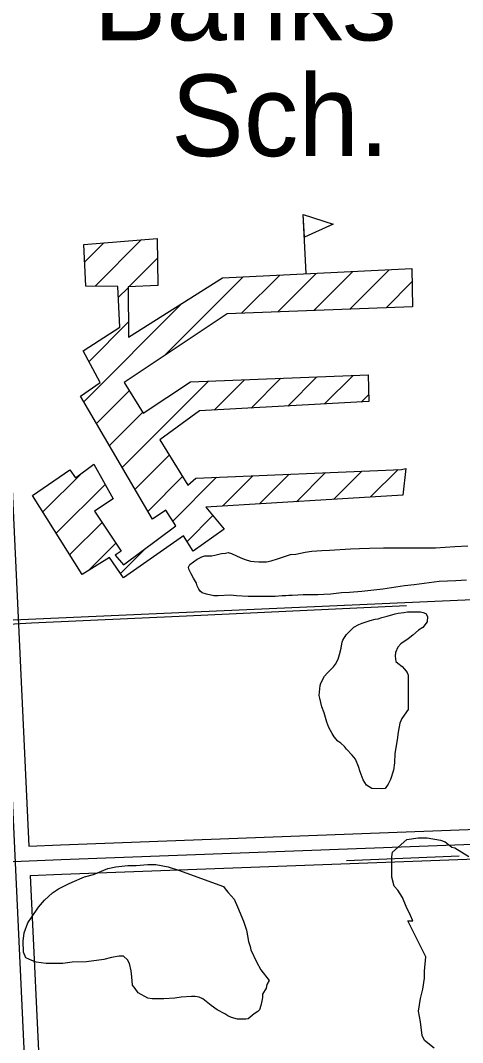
# Model space of a CAD drawing. Extents: x 3313442 to 3351311, y 721974 to 747360.
# Drawn here: x 3332744 to 3333194, y 732187 to 733227 of the extents above; entities that cross this region are included whole.
import ezdxf

# ---------------------------------------------------------------- set-up
doc = ezdxf.new("R2010")
doc.units = 0
for name, color, linetype in [('V-BLDG-IDEN', 7, 'Continuous'), ('V-BLDG-OTLN', 7, 'Continuous'), ('V-ROAD-CNTR', 7, 'Continuous'), ('V-SITE-VEGE', 7, 'Continuous')]:
    doc.layers.add(name, color=color, linetype=linetype)

msp = doc.modelspace()

# ---------------------------------------------------------------- linework, layer by layer
at = {"layer": 'V-BLDG-OTLN'}
for p, q in [((3333034.7, 732969.6), (3333031.7, 733029.6)), ((3332809.2, 732981.5), (3332828.5, 733000.8)), ((3332819.7, 732956.7), (3332867, 733004)), ((3332854.5, 732956.2), (3332883.1, 732984.8)), ((3333005.7, 732930.5), (3333044.8, 732969.7)), ((3333042.4, 732932), (3333082, 732971.5)), ((3333079.2, 732933.4), (3333119.2, 732973.3)), ((3332890.4, 732886), (3332970.5, 732966.1)), ((3332968.9, 732929.1), (3333007.7, 732967.9)), ((3333116, 732934.8), (3333142.5, 732961.3)), ((3332843.4, 732945), (3332853.4, 732955.1)), ((3332808.2, 732839.1), (3332908, 732938.9)), ((3332813.5, 732879.8), (3332853.6, 732919.9)), ((3333015.9, 732834.7), (3333045.6, 732864.4)), ((3333053.3, 732836.8), (3333082.3, 732865.8)), ((3332847.3, 732772.2), (3332935.3, 732860.1)), ((3332941.1, 732830.6), (3332972, 732861.5)), ((3332978.5, 732832.7), (3333008.8, 732863)), ((3332821.2, 732816.8), (3332854.5, 732850.1)), ((3333090.7, 732838.8), (3333098.3, 732846.4)), ((3332834.3, 732794.5), (3332868.2, 732828.4)), ((3332860.3, 732749.9), (3332895.2, 732784.8)), ((3332766.7, 732726.9), (3332806.2, 732766.5)), ((3332873.4, 732727.5), (3332908.8, 732762.9)), ((3332898.9, 732717.7), (3332943.4, 732762.2)), ((3332949.5, 732732.9), (3332980.3, 732763.8)), ((3332987.1, 732735.2), (3333017.3, 732765.4)), ((3333024.7, 732737.4), (3333054.2, 732767)), ((3333062.3, 732739.6), (3333091.2, 732768.6)), ((3333099.8, 732741.9), (3333128.2, 732770.2)), ((3332780.3, 732705.2), (3332830, 732754.9)), ((3332913.4, 732696.9), (3332939.7, 732723.2)), ((3332793.9, 732683.5), (3332826.8, 732716.3)), ((3332813.2, 732667.3), (3332840.9, 732695.1)), ((3332845.6, 732664.4), (3332870.4, 732689.2))]:
    msp.add_line(p, q, dxfattribs=at)
for points in [[(3333031.7, 733029.6), (3333062.2, 733019.6), (3333032.8, 733006.5)], [(3333133, 732743.9), (3332932.6, 732731.9), (3332951, 732709.5), (3332919.5, 732687.1), (3332909.8, 732702.7), (3332848.7, 732660), (3332834.4, 732680.6), (3332806.6, 732663.2), (3332756.2, 732743.7), (3332794, 732769.8), (3332799.9, 732761.7), (3332818.6, 732775.7), (3332838.2, 732740.2), (3332819.2, 732727.7), (3332846.2, 732687.2), (3332840.3, 732683.1), (3332848.7, 732673.1), (3332902, 732712.7), (3332891.8, 732728.9), (3332878.1, 732719.5), (3332805, 732844.6), (3332824.9, 732858.6), (3332807.5, 732891), (3332844.9, 732915), (3332842.8, 732956.4), (3332810.4, 732956.8), (3332808.3, 732999.2), (3332882.8, 733005.3), (3332883.6, 732957.3), (3332853.4, 732956.1), (3332853.7, 732904.7), (3332949.4, 732965), (3333142.3, 732974.5), (3333142.9, 732935.8), (3332954.3, 732928.6), (3332849.2, 732858.6), (3332868.8, 732827.4), (3332916.9, 732859.4), (3333097.6, 732866.4), (3333098.5, 732839.3), (3332925.9, 732829.8), (3332885.6, 732800.2), (3332914.2, 732754.1), (3332922.4, 732761.2), (3333131.5, 732770.3), (3333136.2, 732771)]]:
    msp.add_lwpolyline(points, close=True, dxfattribs=at)
at = {"layer": 'V-ROAD-CNTR'}
for p, q in [((3332912.7, 732621.1), (3333136.8, 732631.6)), ((3333075.8, 732372.4), (3333190.4, 732377))]:
    msp.add_line(p, q, dxfattribs=at)
for points in [[(3332694.5, 733302), (3332784.1, 731387.8)], [(3332709.4, 733302.7), (3332752.3, 732387)], [(3330605.8, 732522.9), (3334476, 732694), (3336331.8, 732776)], [(3330609.1, 732521.6), (3330726.7, 732526.7), (3330931, 732536.4), (3331177.2, 732546.1), (3331338.2, 732554), (3331664.4, 732567.4), (3331950.2, 732579), (3332055.4, 732583.6), (3332350.2, 732595.6), (3332668.8, 732609), (3332755, 732614.2), (3332912.7, 732621.1)], [(3332752.3, 732387), (3332784.6, 732388.3), (3333370.7, 732410.2)], [(3330726.9, 732287.9), (3332785.2, 732373.3), (3333386.4, 732395.8)], [(3332753.7, 732357), (3332785.8, 732358.3), (3333372.2, 732380.2)], [(3332753.7, 732357), (3332764.1, 732136)]]:
    msp.add_lwpolyline(points, dxfattribs=at)
at = {"layer": 'V-SITE-VEGE'}
for points in [[(3332982.3, 732640.8), (3332975.4, 732640.8), (3332963.8, 732641.6), (3332957.5, 732642.4), (3332945.1, 732641.6), (3332940.7, 732641.6), (3332933, 732643.3), (3332928.7, 732644.7), (3332926.7, 732646.3), (3332925.4, 732648.5), (3332923.7, 732651.8), (3332922.9, 732654.6), (3332919.9, 732659.5), (3332917.4, 732663.9), (3332915.2, 732668.9), (3332914.7, 732670.8), (3332916.3, 732673.5), (3332923.7, 732679), (3332928.4, 732681.2), (3332931.4, 732682.3), (3332938.6, 732682.3), (3332941.6, 732682.9), (3332948.5, 732684.8), (3332952.6, 732685), (3332955.1, 732685.6), (3332958.7, 732684.8), (3332968, 732680.4), (3332972.4, 732678.4), (3332977.9, 732677), (3332981.7, 732676.5), (3332986.4, 732676.2), (3332994.1, 732676.2), (3332999.1, 732677.3), (3333005.4, 732679.2), (3333018.6, 732683.6), (3333024.1, 732684.1), (3333033.7, 732686), (3333040.3, 732686.9), (3333050.5, 732687.7), (3333058.2, 732687.9), (3333079.6, 732689.3), (3333089, 732689.6), (3333099.1, 732690.1), (3333113.4, 732690.3), (3333122.8, 732690.3), (3333136.3, 732690.6), (3333166.2, 732690.6), (3333186, 732691.9), (3333199.2, 732692.4)], [(3333197.8, 732657.5), (3333186.8, 732656.7), (3333170, 732656.2), (3333144.5, 732652.9), (3333134.8, 732651.8), (3333121.6, 732649.9), (3333112.6, 732648.3), (3333091.1, 732646.1), (3333078.7, 732645), (3333070.5, 732644.5), (3333059.8, 732643.4), (3333052.6, 732642.9), (3333046.6, 732642.6), (3333031.5, 732642.6), (3333026.2, 732642.3), (3333020.2, 732641.8), (3333016.9, 732641.8), (3333013.9, 732641.5), (3333010.3, 732641.5), (3333002.9, 732641), (3332982.3, 732640.8)], [(3333164.8, 732181.3), (3333155.1, 732189.2), (3333152.7, 732194.1), (3333150.9, 732208.1), (3333149.1, 732219), (3333150.9, 732231.8), (3333153.3, 732241.5), (3333155.2, 732252.5), (3333155.2, 732259.8), (3333156.4, 732274.4), (3333138.2, 732310.9), (3333143.1, 732310.9), (3333140.7, 732316.4), (3333136.4, 732325.5), (3333132.8, 732334.6), (3333127.9, 732342), (3333124.3, 732346.2), (3333121.8, 732355.3), (3333121.9, 732376), (3333122.5, 732380.9), (3333137.1, 732393.6), (3333148.7, 732395.5), (3333157.8, 732395.5), (3333171.2, 732393), (3333176, 732391.2), (3333182.7, 732385.7), (3333185.8, 732385.1), (3333200.3, 732376.5)]]:
    msp.add_lwpolyline(points, dxfattribs=at)
for points in [[(3333138.5, 732525.9), (3333131.9, 732516.9), (3333130, 732512.2), (3333128.3, 732502.9), (3333127.2, 732495.2), (3333124.7, 732481.1), (3333124.4, 732471.8), (3333123.6, 732464.1), (3333120.6, 732454.8), (3333118.1, 732450.1), (3333115.1, 732445.7), (3333111.2, 732445.1), (3333101.6, 732445.7), (3333096.1, 732449), (3333092.5, 732454.5), (3333089.5, 732462.5), (3333087.9, 732468), (3333084.9, 732475.4), (3333081.3, 732479.5), (3333075.8, 732485.6), (3333073.6, 732488.4), (3333069.8, 732491.7), (3333067, 732493.6), (3333063.2, 732498), (3333061, 732501.6), (3333057.7, 732507.6), (3333055.8, 732513.1), (3333053, 732522.7), (3333050.6, 732528.8), (3333048.4, 732537.6), (3333047.8, 732540.3), (3333048.7, 732550.5), (3333049.5, 732552.7), (3333053.4, 732559.8), (3333056.1, 732562.9), (3333062.4, 732569.2), (3333064.6, 732572.2), (3333067.1, 732577.1), (3333068.5, 732581.8), (3333070.2, 732588.4), (3333070.4, 732590.6), (3333071.3, 732594.5), (3333071.8, 732596.4), (3333073.7, 732599.1), (3333075.7, 732602.2), (3333083.1, 732609.6), (3333088.1, 732612.3), (3333091.6, 732613.7), (3333099.6, 732616.4), (3333104.8, 732617.8), (3333107.9, 732618.3), (3333111.7, 732619.7), (3333117.2, 732620.8), (3333125.2, 732623.3), (3333128.2, 732624.1), (3333134, 732624.6), (3333137.6, 732625.2), (3333142.2, 732625.4), (3333146.1, 732625.4), (3333151, 732625.2), (3333153.8, 732624.6), (3333156.5, 732623.5), (3333158.2, 732620.5), (3333157.6, 732615.2), (3333153.5, 732609.5), (3333149.1, 732606.5), (3333143, 732601.5), (3333138.3, 732598), (3333130.9, 732592.7), (3333127.9, 732589.4), (3333125.4, 732583.9), (3333125.1, 732580.1), (3333125.7, 732574.9), (3333127.9, 732573), (3333132.3, 732569.6), (3333134.7, 732566.9), (3333137.5, 732563.6), (3333138.3, 732560.8)], [(3332904.7, 732362.3), (3332950.3, 732345.8), (3332953.3, 732342.2), (3332955.1, 732339.7), (3332961.2, 732333), (3332964.8, 732325.1), (3332970.9, 732310.5), (3332973.9, 732301.4), (3332975.8, 732289.8), (3332977.6, 732284.9), (3332978.2, 732281.3), (3332984.2, 732269.1), (3332988.5, 732261.2), (3332997, 732250.2), (3332994.6, 732246), (3332993.9, 732242.3), (3332990.3, 732236.3), (3332990.3, 732233.2), (3332989.7, 732230.8), (3332988.4, 732224.7), (3332987.2, 732220.4), (3332985.4, 732218.6), (3332981.7, 732216.2), (3332975.7, 732211.3), (3332973.2, 732210.7), (3332964.7, 732210.7), (3332958.6, 732212.6), (3332955, 732214.4), (3332951.9, 732216.2), (3332944, 732220.5), (3332938, 732224.8), (3332929.4, 732231.5), (3332925.8, 732233.3), (3332921.5, 732233.9), (3332917.9, 732233.9), (3332907.5, 732233.3), (3332900.9, 732232.1), (3332889.9, 732231.5), (3332877.7, 732231.5), (3332873.5, 732232.1), (3332863.7, 732237.6), (3332860.7, 732241.9), (3332857.7, 732245.5), (3332857.1, 732254.1), (3332856.5, 732260.1), (3332854.7, 732267.5), (3332852.8, 732271.1), (3332848.6, 732274.8), (3332844.3, 732274.8), (3332836.4, 732273.6), (3332828.5, 732271.7), (3332810.9, 732269.3), (3332796.3, 732268.7), (3332787.1, 732267.5), (3332770.1, 732267.6), (3332759.8, 732268.8), (3332755.5, 732270.6), (3332749.4, 732273.1), (3332747, 732279.1), (3332746.4, 732290.1), (3332747.6, 732298.6), (3332751.3, 732308.9), (3332754.9, 732314.4), (3332762.3, 732324.8), (3332768.3, 732332), (3332776.3, 732339.3), (3332782.4, 732343.6), (3332792.7, 732348.4), (3332796.4, 732350.3), (3332809.1, 732355.7), (3332818.3, 732358.1), (3332832.9, 732364.2), (3332840.8, 732366), (3332853, 732367.2), (3332861.5, 732367.2), (3332873.6, 732368.4), (3332881.5, 732368.4), (3332894.3, 732366)]]:
    msp.add_lwpolyline(points, close=True, dxfattribs=at)

# ---------------------------------------------------------------- texts
at = {"layer": 'V-BLDG-IDEN'}
for s, p in [('Banks', (3332818.2, 733206.8)), ('Sch.', (3332897.1, 733089))]:
    msp.add_text(s, height=83, dxfattribs=at).set_placement(p)

doc.saveas('drawing.dxf')
